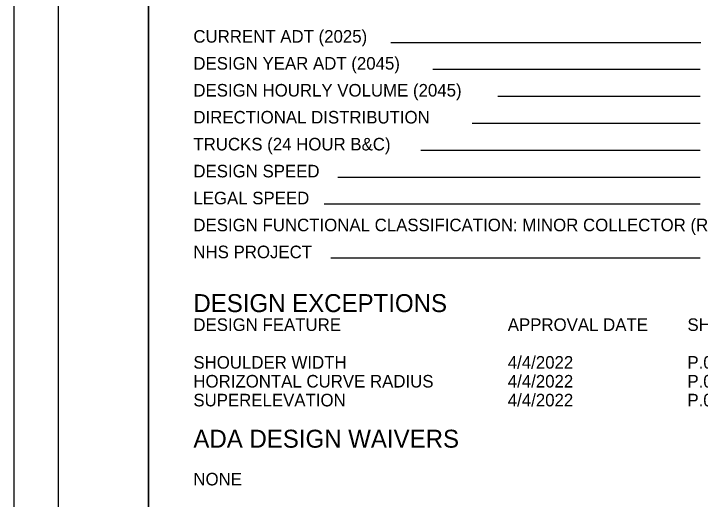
# Model space of a CAD drawing. Extents: x 0 to 2329303, y 0 to 694397.
# Drawn here: x 0 to 7.64, y 5.42 to 10.82 of the extents above; entities that cross this region are included whole.
import ezdxf

# ---------------------------------------------------------------- set-up
doc = ezdxf.new("R2010")
doc.units = 0
for name, color, linetype in [('SH_Border', 7, 'Continuous'), ('SH_Cut_Line', 7, 'Continuous'), ('SH_Data', 7, 'Continuous')]:
    doc.layers.add(name, color=color, linetype=linetype)

msp = doc.modelspace()

# ---------------------------------------------------------------- linework, layer by layer
at = {"layer": 'SH_Border'}
for points in [[(0.5, 21.5), (1.5, 21.5), (1.5, 0.5), (0.5, 0.5)], [(1.5, 21.5), (33.5, 21.5), (33.5, 0.5), (1.5, 0.5)]]:
    msp.add_lwpolyline(points, close=True, dxfattribs=at)
at = {"layer": 'SH_Cut_Line'}
msp.add_lwpolyline([(0, 0), (34, 0), (34, 22), (0, 22)], close=True, dxfattribs=at)
at = {"layer": 'SH_Data'}
for p, q in [((7.648, 10.5), (4.1992, 10.5)), ((7.6424, 10.2), (4.6648, 10.2)), ((7.6424, 9.9), (5.3908, 9.9)), ((7.6424, 9.6), (5.1044, 9.6)), ((7.6424, 9.3), (4.5314, 9.3)), ((7.6424, 9), (3.6091, 9)), ((7.6424, 8.7), (3.4544, 8.7)), ((7.6424, 8.1), (3.5298, 8.1))]:
    msp.add_line(p, q, dxfattribs=at)

# ---------------------------------------------------------------- texts
for s, height, p in [('CURRENT ADT (2025)', 0.14, (2, 10.5)), ('DESIGN YEAR ADT (2045)', 0.14, (2, 10.2)), ('DESIGN HOURLY VOLUME (2045)', 0.14, (2, 9.9)), ('DIRECTIONAL DISTRIBUTION', 0.14, (2, 9.6)), ('TRUCKS (24 HOUR B&C)', 0.14, (2, 9.3)), ('DESIGN SPEED', 0.14, (2, 9)), ('LEGAL SPEED', 0.14, (2, 8.7)), ('DESIGN FUNCTIONAL CLASSIFICATION: MINOR COLLECTOR (RURAL)', 0.14, (2, 8.4)), ('NHS PROJECT', 0.14, (2, 8.1)), ('DESIGN EXCEPTIONS', 0.2, (2, 7.5)), ('DESIGN FEATURE', 0.14, (2, 7.29)), ('APPROVAL DATE', 0.14, (5.5, 7.29)), ('SHEET NUMBER', 0.14, (7.5, 7.29)), ('SHOULDER WIDTH', 0.14, (2, 6.87)), ('4/4/2022', 0.14, (5.5, 6.87)), ('P.03; P.04', 0.14, (7.5, 6.87)), ('4/4/2022', 0.14, (5.5, 6.66)), ('HORIZONTAL CURVE RADIUS', 0.14, (2, 6.66)), ('P.02', 0.14, (7.5, 6.66)), ('SUPERELEVATION', 0.14, (2, 6.45)), ('4/4/2022', 0.14, (5.5, 6.45)), ('P.02', 0.14, (7.5, 6.45)), ('ADA DESIGN WAIVERS', 0.2, (2, 5.99)), ('NONE', 0.14, (2, 5.57))]:
    msp.add_text(s, height=height, dxfattribs=at).set_placement(p)

doc.saveas('drawing.dxf')
